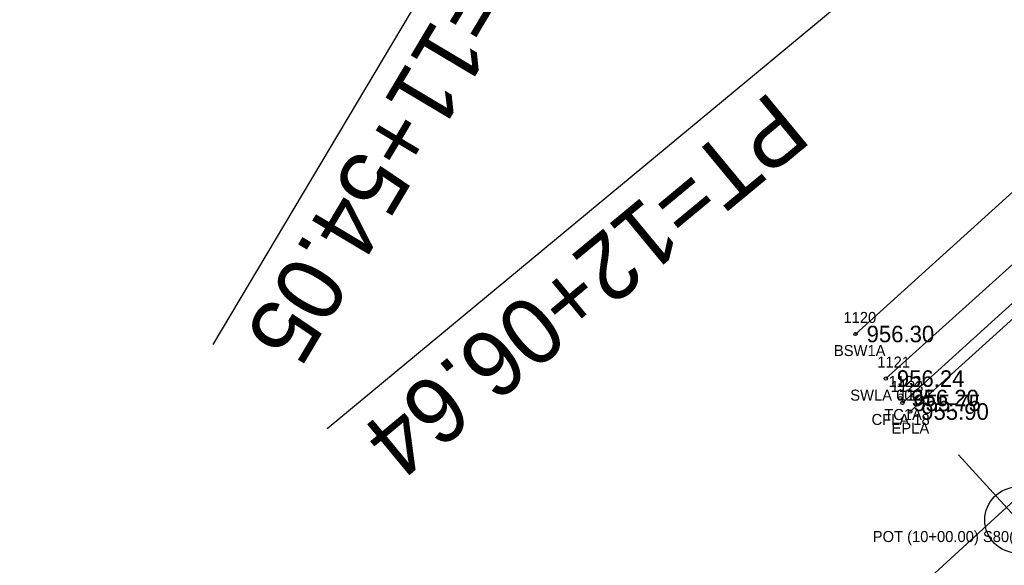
# Model space of a CAD drawing. Extents: x 1575382 to 1578175, y 1099175 to 1101955.
# Drawn here: x 1576264.9 to 1576354.3, y 1099553 to 1099602.5 of the extents above; entities that cross this region are included whole.
import ezdxf

# ---------------------------------------------------------------- set-up
doc = ezdxf.new("R2010")
doc.units = 0
for name, color, linetype in [('RD_EX_Conc', 7, 'Continuous'), ('RD_EX_Conc_txCode', 7, 'Continuous'), ('RD_EX_Road', 7, 'Continuous'), ('RD_EX_Road_txCode', 7, 'Continuous'), ('RD_EX_TX_Conc_ELEV', 7, 'Continuous'), ('RD_EX_TX_Road_ELEV', 7, 'Continuous'), ('RD_EX_UT', 7, 'Continuous'), ('RD_HC_Data', 7, 'Continuous'), ('RD_HC_Data_Tic', 7, 'Continuous'), ('RD_HC_txCode', 7, 'Continuous'), ('RD_SMD_Locator', 7, 'Continuous')]:
    doc.layers.add(name, color=color, linetype=linetype)

msp = doc.modelspace()

# ---------------------------------------------------------------- linework, layer by layer
at = {"layer": 'RD_EX_Conc'}
for p, q in [((1576345.022, 1099567.755), (1576372.484, 1099592.673)), ((1576340.778, 1099574.008), (1576360.313, 1099591.697))]:
    msp.add_line(p, q, dxfattribs=at)
msp.add_lwpolyline([(1576343.522, 1099569.964), (1576363.781, 1099588.213), (1576365.195, 1099586.953), (1576376.121, 1099596.515), (1576380.795, 1099600.714), (1576379.736, 1099601.846)], dxfattribs=at)
at = {"layer": 'RD_EX_Road'}
msp.add_lwpolyline([(1576345.735, 1099566.974), (1576373.249, 1099591.824), (1576377.221, 1099595.34), (1576381.818, 1099599.483), (1576383.698, 1099601.102)], dxfattribs=at)
at = {"layer": 'RD_EX_UT'}
msp.add_line((1576173.795, 1099392.654), (1576417.784, 1099616.336), dxfattribs=at)
at = {"layer": 'RD_HC_Data'}
for p, q in [((1576342.161, 1099673.236), (1576282.43, 1099573.055)), ((1576381.905, 1099639.186), (1576292.822, 1099565.414))]:
    msp.add_line(p, q, dxfattribs=at)
msp.add_circle((1576355.507, 1099557.135), 3, dxfattribs=at)
at = {"layer": 'RD_HC_Data_Tic'}
msp.add_line((1576355.507, 1099557.135), (1576350.111, 1099563.041), dxfattribs=at)
at = {"layer": 'RD_SMD_Locator'}
for centre in [(1576340.778, 1099574.008), (1576343.522, 1099569.964), (1576344.828, 1099568.202), (1576345.022, 1099567.755), (1576345.735, 1099566.974)]:
    msp.add_circle(centre, 0.15, dxfattribs=at)

# ---------------------------------------------------------------- texts
at = {"layer": 'RD_EX_Conc_txCode'}
for s, p in [('1120', (1576339.676, 1099575.008)), ('BSW1A', (1576338.809, 1099572.008)), ('1121', (1576342.742, 1099570.964)), ('1122', (1576343.765, 1099569.202)), ('1123', (1576343.959, 1099568.755)), ('SWLA 60', (1576340.293, 1099567.964)), ('CFLA 18', (1576342.227, 1099565.755)), ('TC1A', (1576343.379, 1099566.202))]:
    msp.add_text(s, height=1, dxfattribs=at).set_placement(p)
at = {"layer": 'RD_EX_Road_txCode'}
for s, p in [('1124', (1576344.672, 1099567.974)), ('EPLA', (1576344.042, 1099564.974))]:
    msp.add_text(s, height=1, dxfattribs=at).set_placement(p)
at = {"layer": 'RD_EX_TX_Conc_ELEV'}
for s, p in [('956.30', (1576341.778, 1099573.258)), ('956.24', (1576344.522, 1099569.214)), ('956.20', (1576345.828, 1099567.452)), ('955.75', (1576346.022, 1099567.005))]:
    msp.add_text(s, height=1.5, dxfattribs=at).set_placement(p)
at = {"layer": 'RD_EX_TX_Road_ELEV'}
msp.add_text('955.90', height=1.5, dxfattribs=at).set_placement((1576346.735, 1099566.224))
at = {"layer": 'RD_HC_Data'}
for s, rotation, p in [('PC=11+54.05', 239.19519, (1576310.591, 1099616.382)), ('PT=12+06.64', 219.62889, (1576333.118, 1099596.188))]:
    msp.add_text(s, height=6, rotation=rotation, dxfattribs=at).set_placement(p)
at = {"layer": 'RD_HC_txCode'}
msp.add_text('POT (10+00.00) S80(N CALHOUN ST', height=1, dxfattribs=at).set_placement((1576342.334, 1099555.135))

doc.saveas('drawing.dxf')
